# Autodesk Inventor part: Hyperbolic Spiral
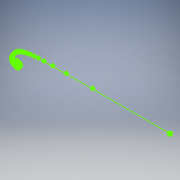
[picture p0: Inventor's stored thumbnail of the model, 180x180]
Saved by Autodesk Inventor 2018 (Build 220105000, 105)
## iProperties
Created: 2008-02
Part Number: Hyperbolic Spiral
Document SubType Name: Modeling
Designer: Autodesk, Inc.
Density: 1 g/cm^3
Material: Generic
Appearance: Default
Author: Autodesk, Inc.
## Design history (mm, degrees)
sketch "Sketch1"
  geometry: 300 further points
  constraints: 300 other
